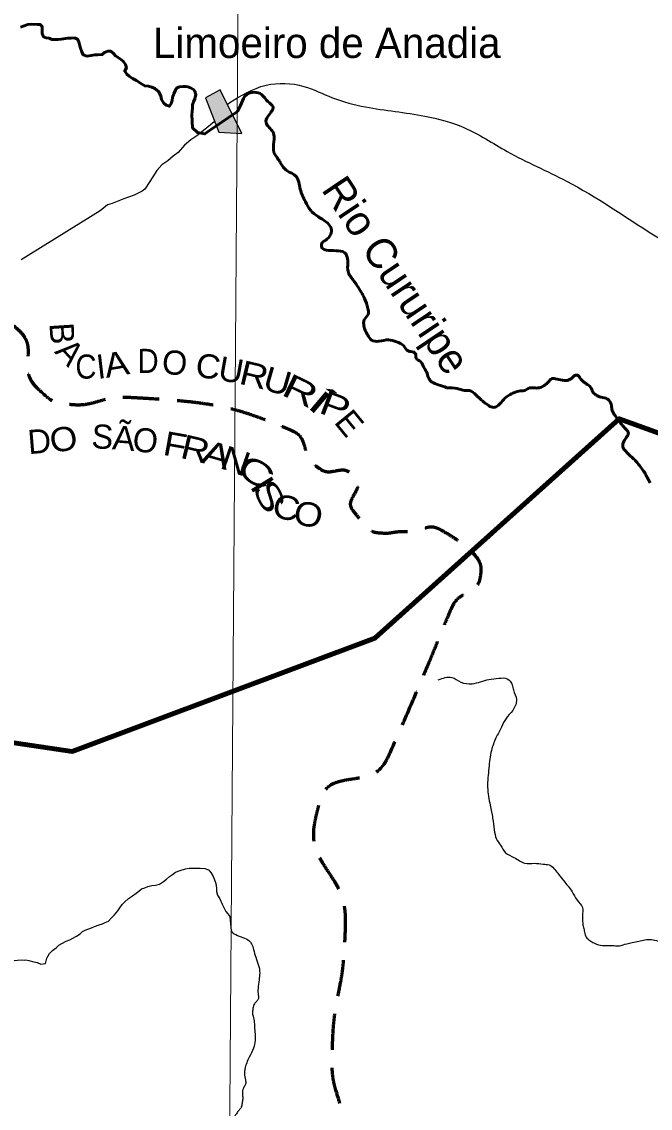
# Model space of a CAD drawing. Extents: x 553962 to 842807, y 8883888 to 9032388.
# Drawn here: x 770713 to 781131, y 8905725 to 8923744 of the extents above; entities that cross this region are included whole.
import ezdxf
from ezdxf.enums import TextEntityAlignment as Align

# ---------------------------------------------------------------- set-up
doc = ezdxf.new("R2010")
doc.units = 0
doc.header["$LTSCALE"] = 200
doc.linetypes.add('MEDIUM_DASHED', pattern=[4.5, 3, -1.5])
for name, color, linetype, lineweight in [('1', 7, 'Continuous', 13), ('10', 7, 'MEDIUM_DASHED', 60), ('12', 7, 'Continuous', 25), ('21', 7, 'Continuous', 25), ('24', 7, 'Continuous', 25), ('9', 7, 'Continuous', 90)]:
    doc.layers.add(name, color=color, linetype=linetype, lineweight=lineweight)
doc.layers.add('41', color=7, linetype='Continuous')
doc.layers.add('49', color=7, linetype='Continuous')

msp = doc.modelspace()

# ---------------------------------------------------------------- hatches: boundary and pattern name
at = {"layer": '21'}
msp.add_hatch(color=256, dxfattribs=at).paths.add_polyline_path([(774002.3, 8922616.4), (773757.5, 8922483.3), (773979.6, 8921912.9), (774358.6, 8921888)])

# ---------------------------------------------------------------- linework, layer by layer
at = {"layer": '1'}
msp.add_lwpolyline([(774987.1, 9020818), (774482.3, 8948876), (774053.6, 8890875.3)], dxfattribs=at)
at = {"layer": '10'}
msp.add_open_spline([(780116.2, 8904162.2), (779769.4, 8904177.9), (779422.6, 8904193.7), (779075.8, 8904209.5), (778695.9, 8904226.8), (778318.1, 8904159.8), (777941, 8904091.2), (777596, 8904028.4), (777262.1, 8903937.2), (776924.3, 8903854.6), (776803.3, 8903825.1), (776686.8, 8903750.4), (776569.7, 8903736.3), (776304.5, 8903704.6), (776099.5, 8903983.3), (775884, 8904233.1), (775776.3, 8904358), (775709.2, 8904488.3), (775694.9, 8904611.7), (775670.8, 8904818.6), (776050.4, 8904994.8), (776049.5, 8905226.7), (776047.7, 8905694.5), (775846.8, 8906171.8), (775860.4, 8906646.1), (775878.9, 8907296.2), (776043.6, 8907946.8), (776074.4, 8908597), (776108.2, 8909310.3), (775454.3, 8910013.8), (775625.2, 8910702.5), (775746.8, 8911192.8), (776625.7, 8911182.1), (776831, 8911648.8), (777030.2, 8912101.5), (777228.1, 8912557.1), (777420.7, 8913014.1), (777556.6, 8913336.6), (777687.6, 8913670.8), (777822.6, 8913984), (777919.6, 8914208.9), (778290.2, 8914361.2), (778319.1, 8914551.8), (778353.9, 8914781.3), (778054.2, 8915076.5), (777751.7, 8915261.5), (777515.3, 8915405.9), (777278.6, 8915289.1), (777042.4, 8915285.1), (776916.2, 8915283), (776790.1, 8915252.3), (776664.1, 8915261.5), (776484.7, 8915274.5), (776355.7, 8915449.8), (776238.5, 8915592.7), (776104.7, 8915755.7), (776352.4, 8916067), (776214.8, 8916207.7), (776079, 8916346.7), (775768.6, 8916238.7), (775623.8, 8916349.7), (775431, 8916497.3), (775387.1, 8916881.7), (775127.3, 8916988.4), (774292.1, 8917331.5), (773439.5, 8917458.1), (772578.9, 8917506.5), (772178.6, 8917529.1), (771773.4, 8917358), (771373.1, 8917411.9), (771257.5, 8917427.5), (771157.3, 8917493.9), (771065.7, 8917577.5), (770748.6, 8917866.7), (770887.1, 8918430.9), (770592.8, 8918689.4), (770430.6, 8918831.9), (770160.1, 8918847), (770001.8, 8918996.9), (769746.9, 8919238.3), (769557.2, 8919552.6), (769292.5, 8919801.2), (768866.2, 8920201.6), (768426.7, 8920562), (767897.5, 8920818.5), (767600.3, 8920962.5), (767240, 8920922), (766928.1, 8920842.2), (766588, 8920755), (766267.8, 8920606.4), (765982.4, 8920369), (765805, 8920221.5), (765830.9, 8919932), (765651.4, 8919801.2), (765249.7, 8919508.7), (764806.4, 8919315.8), (764351, 8919115.2), (764017, 8918968.1), (763624.4, 8918749.5), (763310.7, 8918831.3)], degree=3, dxfattribs=at)
at = {"layer": '12'}
msp.add_lwpolyline([(773904.7, 8922082.2), (773628.7, 8921864.1), (773516.4, 8921787.9), (773409.1, 8921696.4), (773306.7, 8921574.4), (773225, 8921513.4), (773133, 8921437.1), (773036, 8921371.1), (772954.1, 8921274.5), (772836.3, 8921096.4), (772754.3, 8920969.2), (772708.3, 8920933.6), (772575.6, 8920867.6), (772402.2, 8920806.8), (772213.4, 8920730.8), (772136.9, 8920705.4), (772014.3, 8920608.9), (770702.1, 8919796.2)], dxfattribs=at)
msp.add_spline([(774127.4, 8922381.7), (774762.8, 8922691.1), (775387.8, 8922672.2), (775861.3, 8922482.8), (776410.6, 8922331.3), (777395.4, 8922179.8), (778039.4, 8921990.4), (778759.1, 8921592.6), (779744, 8921100.2), (781183.4, 8920210), (782566, 8919452.4), (782831.5, 8919338.8)], degree=3, dxfattribs=at)
at = {"layer": '21'}
msp.add_lwpolyline([(774002.3, 8922616.4), (773757.5, 8922483.3), (773979.6, 8921912.9), (774358.6, 8921888)], close=True, dxfattribs=at)
at = {"layer": '24', "lineweight": 53}
for points in [[(770691.8, 8923656.4), (770753, 8923676.4), (770814.1, 8923696.4), (770870.1, 8923701.1), (770966.7, 8923700.5), (771017.6, 8923700.2), (771053, 8923664.3), (771052.5, 8923598.1), (771052.2, 8923547.1), (771072.2, 8923496.1), (771117.8, 8923475.4), (771168.6, 8923470), (771214.2, 8923449.3), (771265.1, 8923449), (771316, 8923448.7), (771366.8, 8923453.4), (771478.9, 8923473.1), (771529.7, 8923472.7), (771585.7, 8923477.5)], [(771585.7, 8923477.5), (771636.4, 8923456.8), (771656.5, 8923410.8), (771681.3, 8923324.1), (771711.3, 8923242.4), (771731.3, 8923196.4), (771792.2, 8923175.6), (771863.5, 8923185.3), (771924.6, 8923195.1), (771975.4, 8923194.8), (772046.7, 8923199.4), (772082.5, 8923234.9), (772138.6, 8923254.9), (772189.5, 8923254.6), (772235, 8923218.6), (772265.2, 8923177.7), (772310.8, 8923151.9), (772351.3, 8923121.1), (772391.8, 8923090.3), (772432.1, 8923034), (772447, 8922982.9), (772421.1, 8922922), (772456.4, 8922875.9), (772491.8, 8922840), (772547.5, 8922804), (772613.3, 8922767.9), (772689.3, 8922721.6), (772755.2, 8922680.4), (772816.2, 8922674.9), (772866.9, 8922659.3), (772917.6, 8922638.6), (772978.3, 8922587.3), (773018.5, 8922515.7), (773028.2, 8922454.6), (773063.5, 8922398.3), (773109, 8922362.3), (773159.7, 8922341.6), (773190.6, 8922387.3), (773206.2, 8922438.1), (773211.6, 8922489), (773235.3, 8922546.6), (773253.2, 8922600.3), (773278.8, 8922641.4), (773324.8, 8922663), (773387.4, 8922671.9), (773432.1, 8922671.9), (773467.8, 8922663), (773512.6, 8922645.1), (773557.3, 8922618.2), (773584.1, 8922591.4), (773593, 8922555.6), (773598.5, 8922537.5), (773582.7, 8922466.3), (773562, 8922415.5), (773541.3, 8922364.7), (773541, 8922313.7), (773535.5, 8922252.6), (773530.1, 8922201.7), (773543.8, 8921982.6), (773624.7, 8921905.7), (773745.1, 8921884.1), (773825.5, 8921937.8), (774289.1, 8922253.7)]]:
    msp.add_lwpolyline(points, dxfattribs=at)
at = {"layer": '24'}
for points in [[(771104.7, 8908124.9), (771111.7, 8908148.9), (771127.4, 8908215), (771173.7, 8908291.1), (771219.8, 8908341.8), (771281.2, 8908387.2), (771327.2, 8908427.7), (771378.3, 8908457.9), (771449.7, 8908493.1), (771511, 8908518.2), (771556.9, 8908543.4), (771618.2, 8908578.6), (771679.5, 8908619), (771720.4, 8908654.4), (771766.4, 8908679.6), (771868.3, 8908714.6), (771919.4, 8908739.7), (771995.8, 8908764.7), (772051.9, 8908784.7), (772097.8, 8908804.8), (772148.9, 8908829.9), (772195, 8908875.5), (772251.3, 8908931.1), (772307.7, 8908997), (772338.6, 8909047.7), (772379.6, 8909103.5), (772415.5, 8909144), (772482.1, 8909204.7), (772548.4, 8909245.1), (772609.8, 8909290.5), (772655.8, 8909325.9), (772696.7, 8909361.3), (772752.8, 8909381.3), (772803.8, 8909401.3), (772870.1, 8909421.3), (772931.2, 8909426), (772997.4, 8909440.8), (773063.8, 8909486.3), (773109.9, 8909526.7), (773161, 8909567.1), (773212.1, 8909602.5), (773263.2, 8909637.8), (773339.7, 8909667.9), (773426.3, 8909692.8), (773487.5, 8909707.7), (773604.5, 8909706.9), (773670.6, 8909706.5), (773746.8, 8909700.9), (773807.7, 8909680.2), (773848.1, 8909634), (773883.2, 8909567.6), (773908.3, 8909511.4), (773928.2, 8909450.2), (773942.9, 8909373.7), (773942.6, 8909317.6), (773957.4, 8909256.4), (773997.7, 8909200.1), (774032.7, 8909108.2), (774072.8, 8909031.5), (774092.9, 8908985.6), (774128.2, 8908949.7), (774163.5, 8908903.6), (774185.6, 8908665.7)], [(770408.6, 8908080.8), (770464.6, 8908100.9), (770526, 8908151.4), (770590.1, 8908175.8), (770641.1, 8908179.8), (770707.8, 8908187.6), (770758.8, 8908179.8), (770782.3, 8908183.7), (770829.4, 8908175.8), (770911.8, 8908152.3), (770970.6, 8908144.4), (771029.5, 8908116.9), (771104.7, 8908124.9)]]:
    msp.add_lwpolyline(points, dxfattribs=at)
at = {"layer": '24', "lineweight": 53}
for points in [[(774289.1, 8922253.7), (774354.7, 8922391.4), (774442, 8922536.8), (774689.1, 8922536.8), (774790.9, 8922420.5), (774878.1, 8922333.3), (774790.9, 8922173.4), (774761.8, 8922071.6), (774878.1, 8921911.7), (774892.6, 8921751.8), (774892.6, 8921577.3), (774965.3, 8921461), (775110.7, 8921272), (775256.1, 8921184.8), (775328.8, 8920966.7), (775414.3, 8920761.6), (775502.1, 8920615.2), (775624.1, 8920512.8), (775785.1, 8920400.6), (775843.6, 8920312.7), (775833.9, 8920220.1), (775750.9, 8920122.5), (775692.4, 8920078.6), (775692.4, 8919990.8), (775765.6, 8919956.6), (775921.7, 8919946.9), (776063.2, 8919912.7), (776097.3, 8919868.8), (776116.8, 8919751.7), (776126.6, 8919585.9), (776175.3, 8919502.9), (776272.9, 8919366.3), (776394.9, 8919151.7), (776448.5, 8918990.7), (776453.4, 8918888.2), (776390, 8918800.4), (776385.1, 8918698), (776409.5, 8918619.9), (776448.5, 8918546.8), (776512, 8918463.8), (776633.9, 8918444.3), (776790, 8918468.7), (776926.6, 8918434.6), (777043.7, 8918366.2), (777116.9, 8918283.3), (777209.6, 8918263.8), (777243.7, 8918224.8), (777248.6, 8918166.2), (777326.7, 8918104.2), (777375.5, 8918011.4), (777424.2, 8917938.2), (777453.5, 8917840.6), (777512, 8917767.4), (777614.5, 8917723.5), (777760.8, 8917674.7)], [(777760.8, 8917674.7), (777931.6, 8917660), (778053.6, 8917630.7), (778136.5, 8917625.8), (778238.9, 8917557.5), (778356, 8917450.1), (778453.6, 8917376.9), (778536.5, 8917347.6), (778609.7, 8917381.8), (778702.4, 8917479.4), (778790.2, 8917552.6), (778868.2, 8917591.7), (778980.5, 8917621), (779063.4, 8917635.6), (779126.8, 8917669.8), (779224.4, 8917669.8), (779307.3, 8917679.5), (779375.6, 8917713.7), (779439, 8917767.4), (779497.6, 8917826), (779585.4, 8917816.2), (779702.5, 8917796.7), (779756.1, 8917796.7), (779843.9, 8917845.5), (779883, 8917879.7), (779931.7, 8917879.7), (779965.9, 8917835.7), (780029.3, 8917767.4), (780109.8, 8917713.7), (780163.5, 8917645.4), (780187.8, 8917586.8), (780236.6, 8917552.6), (780290.3, 8917523.3), (780392.7, 8917498.9), (780451.3, 8917459.9), (780485.4, 8917381.8), (780500.1, 8917293.9), (780548.8, 8917211), (780621.5, 8917109.9), (780695, 8917023.2), (780736.5, 8916974.2), (780766.6, 8916932.7), (780764.7, 8916906.3), (780717.6, 8916827.1), (780676.1, 8916734.8), (780679.9, 8916678.2), (780713.8, 8916634.8), (780774.2, 8916568.9), (780834.5, 8916512.3), (780885.4, 8916463.3), (780938.2, 8916401.1), (780996.6, 8916325.7), (781043.7, 8916254.1), (781083.3, 8916178.7), (781130.5, 8916097.6)]]:
    msp.add_spline(points, degree=3, dxfattribs=at)
at = {"layer": '24'}
for points in [[(777617.6, 8912828.3), (777839.2, 8912869.9), (777991.6, 8912793.7), (778178.6, 8912766), (778455.7, 8912835.2), (778621.9, 8912856), (778760.5, 8912849.1), (778843.6, 8912745.2), (778864.3, 8912662.1), (778912.8, 8912502.8), (778850.5, 8912322.7), (778739.7, 8912191.1), (778663.5, 8912045.6), (778573.4, 8911865.5), (778497.2, 8911657.7), (778455.7, 8911366.8), (778434.9, 8911048.2), (778476.5, 8910750.4), (778518, 8910535.6), (778545.7, 8910341.7), (778580.4, 8910189.3), (778649.6, 8910085.4), (778732.8, 8909960.8), (778871.3, 8909884.6), (779051.4, 8909787.6), (779210.7, 8909787.6), (779356.1, 8909773.7), (779453.1, 8909759.9), (779598.6, 8909621.3), (779695.5, 8909496.7), (779834.1, 8909316.6), (779917.2, 8909178.1), (780007.2, 8909053.4), (780007.2, 8908921.8), (780009.3, 8908822.2), (780018.8, 8908742.2), (780037.6, 8908666.9), (780056.4, 8908582.2), (780110.5, 8908518.7), (780178.7, 8908476.4), (780303.4, 8908427), (780439.8, 8908424.6), (780552.7, 8908419.9), (780618.6, 8908419.9), (780740.9, 8908452.8), (780832.7, 8908471.7), (780938.5, 8908495.2), (781042, 8908518.7), (781150.2, 8908521.1), (781263.2, 8908495.2), (781387.8, 8908429.3), (781472.5, 8908377.6), (781569, 8908323.5), (781672.5, 8908252.9), (781759.5, 8908175.3)], [(774185.6, 8908665.7), (774206.6, 8908640.3), (774262.2, 8908604.4), (774377, 8908558), (774477.9, 8908507), (774520.8, 8908450.2), (774556.7, 8908357.5), (774590.3, 8908228.8), (774637.8, 8908089.7), (774657, 8907966.8), (774646.5, 8907852.1), (774629.1, 8907712.9), (774632.6, 8907601.7), (774636.1, 8907542.5), (774608.3, 8907500.8), (774570, 8907459.1), (774545.7, 8907382.6), (774537.9, 8907322.4), (774546.2, 8907252.2), (774566.8, 8907147.9), (774572, 8907048.8), (774582.3, 8906929.1), (774580.2, 8906846.2), (774553.4, 8906721.3), (774483.2, 8906572.6), (774441.9, 8906478.6), (774411, 8906374.3), (774403.7, 8906304.8), (774420.2, 8906190.2), (774426.4, 8906138.5), (774400.6, 8906085.9), (774376.9, 8906034.2), (774372.8, 8905948.5), (774375.9, 8905877.3), (774365.5, 8905808.1), (774350, 8905739.9), (774314.9, 8905694.5), (774270.6, 8905633.5), (774243.7, 8905593.3), (774221, 8905553), (774216.9, 8905506.5), (774205.5, 8905472.4), (774207.6, 8905414.6), (774213.8, 8905325.8), (774211.7, 8905257.6), (774247.8, 8905209.1), (774287.1, 8905162.6), (774350, 8905098.6), (774387.2, 8905056.3), (774415, 8904970.4), (774420.2, 8904906.4), (774418.1, 8904863), (774400.6, 8904807.3), (774394.4, 8904756.7), (774392.3, 8904706.1)]]:
    msp.add_spline(points, degree=3, dxfattribs=at)
at = {"layer": '9'}
msp.add_lwpolyline([(765974.5, 8912469.6), (771548.8, 8911642.3), (776566.8, 8913518.4), (780614.1, 8917160.1), (782189.6, 8916587.3), (785656.2, 8919415.9), (791912, 8922868)], dxfattribs=at)

# ---------------------------------------------------------------- texts
at = {"layer": '10'}
for s, rotation, p in [('B', 273.7, (771182.6, 8918561.9)), ('A', 312.27, (771365.1, 8918132.2)), ('I', 6.726, (772047.4, 8917827.9)), ('O', 355.328, (773232.9, 8917891.1)), ('E', 309.301, (775989.3, 8916961)), ('D', 4.609, (771020.3, 8916587.2)), ('S', 356.776, (772039.9, 8916663.1)), ('O', 353.119, (772739.5, 8916603.3))]:
    msp.add_text(s, height=400, rotation=rotation, dxfattribs=at).set_placement(p, align=Align.CENTER)
for s, rotation, width, p in [('C', 359.4, 0.9, (771774.6, 8917825.1)), ('A', 9.637, 1.15, (772314.8, 8917870.3)), ('D', 0.236, 0.9, (772808.5, 8917919.6)), ('C', 352.107, 1.05, (773776, 8917831)), ('U', 349.875, 1.05, (774148.5, 8917770.9)), ('R', 346.703, 1.2, (774520.9, 8917691.9)), ('U', 343.896, 1.15, (774897.3, 8917591.2)), ('R', 334.15, 1.45, (775247.1, 8917444.1)), ('Í', 319.844, 1.7, (775521.5, 8917280.7)), ('P', 339.291, 1.35, (775841.5, 8917181.7)), ('Ã', 355.328, 1.05, (772390.6, 8916638.8)), ('O', 9.637, 1.1, (771438, 8916625.6)), ('F', 349.875, 1.15, (773220.9, 8916530.8)), ('R', 346.703, 1.2, (773547.6, 8916462.3)), ('A', 343.896, 1.3, (773886.4, 8916372.5)), ('N', 340.873, 1.2, (774194.5, 8916271.5)), ('C', 328.723, 1.55, (774493, 8916104)), ('I', 301.588, 1.25, (774530.3, 8915964.2)), ('S', 297.643, 1.5, (774641.5, 8915785)), ('C', 347.533, 1.15, (775056.3, 8915491.9)), ('O', 347.535, 1.15, (775421.7, 8915378.7))]:
    msp.add_text(s, height=400, rotation=rotation, dxfattribs=dict(at, width=width)).set_placement(p, align=Align.CENTER)
at = {"layer": '41'}
msp.add_text('Limoeiro de Anadia', height=500, dxfattribs=at).set_placement((772888, 8923143.2))
at = {"layer": '49'}
msp.add_text('Rio Cururipe', height=500, rotation=303.874, dxfattribs=at).set_placement((776713.2, 8919402.4), align=Align.CENTER)

doc.saveas('drawing.dxf')
